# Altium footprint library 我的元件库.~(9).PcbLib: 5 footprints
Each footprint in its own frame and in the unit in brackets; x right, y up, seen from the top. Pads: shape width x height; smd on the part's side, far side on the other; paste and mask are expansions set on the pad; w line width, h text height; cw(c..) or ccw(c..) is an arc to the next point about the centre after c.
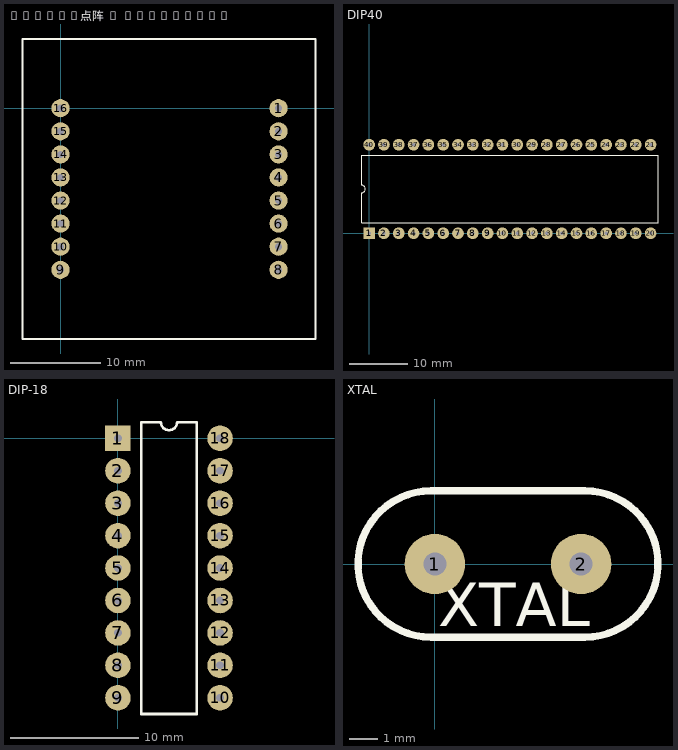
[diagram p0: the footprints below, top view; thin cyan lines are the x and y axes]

## 8-8LED点阵 - duplicate [mm]
height 4
pads (16):
  round 2 hole 0.8: 1(24.003,0) 2(24.003,-2.54) 3(24.003,-5.08) 4(24.003,-7.62) 5(24.003,-10.16) 6(24.003,-12.7) 7(24.003,-15.24) 8(24.003,-17.78) 9(-0.003,-17.78) 10(-0.003,-15.24) 11(-0.003,-12.7) 12(-0.003,-10.16) 13(-0.003,-7.62) 14(-0.003,-5.08) 15(-0.003,-2.54) 16(-0.003,0)
Top Overlay:
  lines w0.2: -4.191,-25.4 28.067,-25.4 28.067,7.62 15.429,7.62 -4.191,7.62 -4.191,-25.4

## DIP40 [mm]
pads (40):
  rect 2x2 hole 0.6: 1(0,0)
  round 2 hole 0.6: 2(2.54,0) 3(5.08,0) 4(7.62,0) 5(10.16,0) 6(12.7,0) 7(15.24,0) 8(17.78,0) 9(20.32,0) 10(22.86,0) 11(25.4,0) 12(27.94,0) 13(30.48,0) 14(33.02,0) 15(35.56,0) 16(38.1,0) 17(40.64,0) 18(43.18,0) 19(45.72,0) 20(48.26,0) 21(48.26,15.2) 22(45.72,15.2) 23(43.18,15.2) 24(40.64,15.2) 25(38.1,15.2) 26(35.56,15.2) 27(33.02,15.2) 28(30.48,15.2) 29(27.94,15.2) 30(25.4,15.2) 31(22.86,15.2) 32(20.32,15.2) 33(17.78,15.2) 34(15.24,15.2) 35(12.7,15.2) 36(10.16,15.2) 37(7.62,15.2) 38(5.08,15.2) 39(2.54,15.2) 40(0,15.2)
Top Overlay:
  lines w0.2: -1.27,1.835 -1.27,6.965 ccw(c-1.27,7.6) -1.27,8.235 -1.27,13.365 49.53,13.365 49.53,1.835 -1.27,1.835

## DIP-18 [mm]
pads (18):
  rect 2x2 hole 0.6: 1(0,0)
  round 2 hole 0.6: 2(0,-2.54) 3(0,-5.08) 4(0,-7.62) 5(0,-10.16) 6(0,-12.7) 7(0,-15.24) 8(0,-17.78) 9(0,-20.32) 10(8,-20.32) 11(8,-17.78) 12(8,-15.24) 13(8,-12.7) 14(8,-10.16) 15(8,-7.62) 16(8,-5.08) 17(8,-2.54) 18(8,0)
Top Overlay:
  lines w0.2: 1.835,-21.59 1.835,1.27 3.365,1.27 ccw(c4,1.27) 4.635,1.27 6.165,1.27 6.165,-21.59 1.835,-21.59

## PCBComponent_1 [mm]

## XTAL [mm]
height 2.5
pads (2):
  round 2.1 hole 0.8: 1(0,0) 2(5.08,0)
Top Overlay:
  lines w0.254: -0.127,-2.54 cw(c-0.127,0) -0.127,2.54 5.207,2.54 cw(c5.207,0) 5.207,-2.54 -0.127,-2.54
  text "XTAL" at 0.127,-2.159 h1.52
